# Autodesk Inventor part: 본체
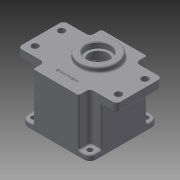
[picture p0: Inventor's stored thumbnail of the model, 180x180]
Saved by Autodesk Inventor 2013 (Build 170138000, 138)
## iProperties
Created: 2015-07
Part Number: 본체
Material: 일반
Document SubType Name: Modeling
Designer: user
Density: 1 g/cm^3
Author: user
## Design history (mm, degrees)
sketch "스케치3"
  geometry: L1 (45, 30)-(45, -30); L2 (30, -45)-(-30, -45); L3 (-45, -30)-(-45, 30); L4 (30, 45)-(30, 30); L5 (30, 30)-(45, 30); L6 (-30, 30)-(-45, 30); L7 (-30, 45)-(-30, 30); L8 (-30, -30)-(-45, -30); L9 (-30, -45)-(-30, -30); L10 (30, -45)-(30, -30); L11 (30, -30)-(45, -30); L12 (30, 45)-(-30, 45); 3 further points
  constraints: 24 end point, 2 midpoint, 2 parallel, 1 horizontal alignment, 1 perpendicular, 1 vertical alignment
  dimensions: "d7" = 15 distance of L4.start L4.end; "d8" = 15 distance of L4.end L1.start; "d9" = 15 distance of L6.start L3.end; "d10" = 60 distance of L4.start L7.start; "d11" = 90 distance between parallel lines of L1 L3; "d12" = 45 distance from line of L1 point (0, 0); "d13" = 15 distance between parallel lines of L3 L9; "d14" = 15 distance between parallel lines of L1 L10; "d15" = 60 distance of L2.start L2.end; "d16" = 15 distance between parallel lines of L2 L8; "d17" = 15 distance between parallel lines of L2 L11; "d18" = 15 distance between parallel lines of L12 L6; "d19" = 90 distance between parallel lines of L2 L12; "d20" = 45 distance from line of L12 point (0, 0); "d21" = 30 distance from line of point (0, 0) L4; "d22" = 45 distance from line of point (0, -45) L1
extrude "돌출2" new body sketch "스케치3" distance "d23" = 70; taper "d24" = 0 deg
sketch "스케치4"
  geometry: L1 (-30, 45)-(-30, 30) reference; L2 (-30, 30)-(-45, 30) reference; L3 (-45, 30)-(-45, -30) reference; L4 (-45, -30)-(-30, -30) reference; L5 (-30, -30)-(-30, -45) reference; L6 (-30, -45)-(30, -45) reference; L7 (30, -45)-(30, -30) reference; L8 (30, -30)-(45, -30) reference; L9 (45, -30)-(45, 30) reference; L10 (45, 30)-(30, 30) reference; L11 (30, 30)-(30, 45) reference; L12 (30, 45)-(-30, 45) reference; L13 (0, 0)-(0, 45); L14 (0, 45)-(30, 45); L15 (30, 45)-(30, 30); L16 (30, 30)-(65, 30); L17 (65, 30)-(65, -30); L18 (65, -30)-(30, -30); L19 (30, -30)-(30, -45); L20 (30, -45)-(0, -45); L21 (0, 45)-(-30, 45); L22 (-30, 45)-(-30, 30); L23 (-30, 30)-(-65, 30); L24 (-65, 30)-(-65, -30); L25 (-65, -30)-(-30, -30); L26 (-30, -30)-(-30, -45); L27 (-30, -45)-(0, -45)
  constraints: 30 end point, 3 perpendicular, 2 collinear, 2 midpoint, 2 symmetric about line
  dimensions: "d25" = 30 distance of L13.end L11.end (derived); "d26" = 35 distance of L10.end L16.end; "d27" = 60 distance of L16.end L17.end; "d28" = 35 distance of L17.end L7.end (derived); "d29" = 15 distance of L7.end L6.end (derived)
extrude "돌출3" join sketch "스케치4" distance "d30" = 12; taper "d31" = 0 deg
sketch "스케치5"
  geometry: L1 (-45, 45)-(45, 45); L2 (45, 45)-(45, -45); L3 (45, -45)-(-45, -45); L4 (-45, -45)-(-45, 45); 3 further points
  constraints: 8 end point, 2 midpoint, 2 parallel, 1 horizontal, 1 horizontal alignment, 1 perpendicular, 1 vertical alignment
  dimensions: "d32" = 90 distance of L2.end L3.end; "d33" = 90 distance of L1.end L2.end
extrude "돌출4" join sketch "스케치5" distance "d34" = 7; taper "d35" = 0 deg
fillet "모깎기1" dims "d36" = 5
fillet "모깎기2" dims "d37" = 8
sketch "스케치6"
  geometry: C1 r 40 at (0, 0); 1 further point
  constraints: 1 centre point, 1 coincident
  dimensions: "d38" = 80 diameter of C1
extrude "돌출5" cut sketch "스케치6" distance "d39" = 9; taper "d40" = 0 deg
sketch "스케치7"
  geometry: L1 (0, 0)-(24.749, 24.749); L2 (0, 0)-(35, 0); C1 r 40 at (0, 0) reference; A1 r 4 centre (24.749, 24.749) between (21.809, 27.462) and (27.462, 21.809); A2 r 3.5 centre (19.238, 29.836) between (21.762, 27.412) and (21.134, 32.777); A3 r 3.5 centre (29.836, 19.238) between (32.777, 21.134) and (27.412, 21.762); A4 r 3.5 centre (-29.836, 19.238) between (-27.412, 21.762) and (-32.777, 21.134); A5 r 4 centre (-24.749, 24.749) between (-27.462, 21.809) and (-21.809, 27.462); A6 r 3.5 centre (-19.238, 29.836) between (-21.134, 32.777) and (-21.762, 27.412); A7 r 3.5 centre (-19.238, -29.836) between (-21.762, -27.412) and (-21.134, -32.777); A8 r 4 centre (-24.749, -24.749) between (-21.809, -27.462) and (-27.462, -21.809); A9 r 3.5 centre (-29.836, -19.238) between (-32.777, -21.134) and (-27.412, -21.762); A10 r 3.5 centre (29.836, -19.238) between (27.412, -21.762) and (32.777, -21.134); A11 r 4 centre (24.749, -24.749) between (27.462, -21.809) and (21.809, -27.462); A12 r 3.5 centre (19.238, -29.836) between (21.134, -32.777) and (21.762, -27.412); A13 r 39 centre (0, 0) between (21.134, 32.777) and (-21.134, 32.777); A14 r 39 centre (0, 0) between (-32.777, 21.134) and (-32.777, -21.134); A15 r 39 centre (0, 0) between (-21.134, -32.777) and (21.134, -32.777); A16 r 39 centre (0, 0) between (32.777, -21.134) and (32.777, 21.134)
  constraints: 40 point on circle, 16 centre point, 5 tangent, 4 end point, 3 coincident, 1 equal length, 1 horizontal, 49 other
  dimensions: "d43" = 35 distance of L1.start L1.end; "d44" = 45 deg angle of L2 L1; "d45" = 8 diameter of A1; "d46" = 7 diameter of A2; "d47" = 7 diameter of A3; "d50" = 360 deg dimension on A13.centre A2.centre (derived); "d52" = 21.76231 distance from line of A3.end L2; "d53" = 21.76231 distance from line of A10.start L2
extrude "돌출6" cut sketch "스케치7" distance "d54" = 52; taper "d55" = 0 deg
hole "구멍1" diameter "d58" = 3.459; stored, may be unused: countersink angle "d62" = 90 deg, drill point angle "d64" = 118 deg; dims "d56" = 10, "d57" = 10, "d59" = 12, "d60" = 4, "d61" = 2, "d63" = 15
sketch "스케치9"
  geometry: L1 (0, 0)-(0, 11); L2 (0, 0)-(0, -20); A1 r 39 centre (0, 0) between (32.777, -21.134) and (32.777, 21.134) reference; A2 r 20.5 centre (0, 11) between (11.115, -6.225) and (-11.115, -6.225); A3 r 14 centre (0, -20) between (-10.493, -10.732) and (10.493, -10.732); A4 r 3 centre (12.742, -8.746) between (11.115, -6.225) and (10.493, -10.732); A5 r 3 centre (-12.742, -8.746) between (-10.493, -10.732) and (-11.115, -6.225)
  constraints: 8 point on circle, 4 centre point, 4 end point, 4 tangent, 2 coincident, 1 collinear, 1 vertical
  dimensions: "d68" = 11 distance of L1.start L1.end; "d69" = 41 diameter of A2; "d70" = 20 distance of L1.start L2.end; "d71" = 28 diameter of A3; "d72" = 6 diameter of A4; "d73" = 6 diameter of A5
extrude "돌출7" join sketch "스케치9" distance "d74" = 7; taper "d75" = 0 deg
sketch "스케치10"
  geometry: L1 (-30, 30)-(-60, 30) reference; L2 (0, 0)-(0, 11); C1 r 25 at (0, 11)
  constraints: 2 end point, 1 centre point, 1 coincident, 1 perpendicular
  dimensions: "d76" = 11 distance of L2.start L2.end; "d77" = 50 diameter of C1
extrude "돌출8" join sketch "스케치10" distance "d78" = 7; taper "d79" = 0 deg
hole "구멍2" diameter "d82" = 25; stored, may be unused: countersink angle "d86" = 90 deg, drill point angle "d88" = 118 deg; dims "d80" = 10, "d81" = 10, "d83" = 12, "d84" = 32, "d85" = 8, "d87" = 15
sketch "스케치11"
  geometry: C1 r 12.5 at (0, 11) reference; C2 r 17.5 at (0, 11); A1 r 20.5 centre (0, 11) between (11.115, -6.225) and (-11.115, -6.225) reference; 1 further point
  constraints: 1 centre point, 1 coincident
  dimensions: "d89" = 35 diameter of C2
extrude "돌출9" cut sketch "스케치11" distance "d90" = 10; taper "d91" = 0 deg
hole "구멍3" diameter "d94" = 19; stored, may be unused: countersink angle "d98" = 90 deg, drill point angle "d100" = 0 deg; dims "d92" = 10, "d93" = 10, "d95" = 12, "d96" = 22, "d97" = 7, "d99" = 8
fillet "모깎기3" dims "d101" = 2
fillet "모깎기4" dims "d102" = 2
fillet "모깎기5" dims "d103" = 2
chamfer "모따기1" distance "d104" = 1; stored, may be unused: second distance "d105" = 2, angle "d106" = 45 deg
fillet "모깎기6" dims "d107" = 1
chamfer "모따기2" distance "d108" = 1; stored, may be unused: second distance "d109" = 2, angle "d110" = 45 deg
fillet "모깎기7" dims "d111" = 0.3
fillet "모깎기8" dims "d112" = 5
fillet "모깎기9" dims "d113" = 2
fillet "모깎기10" dims "d114" = 2
sketch "스케치13"
  geometry: L1 (35, 30)-(43.536, 30) reference; L2 (60, 28)-(47, 28) reference; L3 (63, -25)-(63, 25) reference; L4 (47, -28)-(60, -28) reference; L5 (43.536, -30)-(35, -30) reference; L6 (30, -35)-(30, -43) reference; L7 (28, -45)-(-28, -45) reference; L8 (-30, -43)-(-30, -35) reference; L9 (-35, -30)-(-43, -30) reference; L10 (-47, -28)-(-47, 28) reference; L11 (-43, 30)-(-35, 30) reference; L12 (-30, 35)-(-30, 43) reference; L13 (-28, 45)-(28, 45) reference; L14 (30, 43)-(30, 35) reference; L15 (47, 28)-(47, -28) reference; L16 (-60, -28)-(-47, -28) reference; L17 (-63, 25)-(-63, -25) reference; L18 (-47, 28)-(-60, 28) reference; L19 (65, -25)-(65, 25) reference; L20 (65, 0)-(65, 17.5); L21 (65, 17.5)-(55, 17.5); C1 r 11 at (0, -20) reference; C2 r 17.5 at (0, 11) reference; C3 r 4.5 at (55, 17.5); A1 r 5 centre (35, 35) between (30, 35) and (35, 30) reference; A2 r 3 centre (60, 25) between (63, 25) and (60, 28) reference; A3 r 3 centre (60, -25) between (60, -28) and (63, -25) reference; A4 r 5 centre (35, -35) between (35, -30) and (30, -35) reference; A5 r 2 centre (28, -43) between (28, -45) and (30, -43) reference; A6 r 2 centre (-28, -43) between (-30, -43) and (-28, -45) reference; A7 r 5 centre (-35, -35) between (-30, -35) and (-35, -30) reference; A8 r 2 centre (-43, -28) between (-44, -29.732) and (-43, -30) reference; A9 r 2 centre (-43, 28) between (-43, 30) and (-44, 29.732) reference; A10 r 5 centre (-35, 35) between (-35, 30) and (-30, 35) reference; A11 r 2 centre (-28, 43) between (-28, 45) and (-30, 43) reference; A12 r 2 centre (28, 43) between (30, 43) and (28, 45) reference; A13 r 3 centre (-60, -25) between (-63, -25) and (-60, -28) reference; A14 r 3 centre (-60, 25) between (-60, 28) and (-63, 25) reference; A15 r 14 centre (0, -20) between (-10.493, -10.732) and (10.493, -10.732) reference; A16 r 3 centre (-12.742, -8.746) between (-10.493, -10.732) and (-11.115, -6.225) reference; A17 r 20.5 centre (0, 11) between (11.115, -6.225) and (-11.115, -6.225) reference; A18 r 3 centre (12.742, -8.746) between (11.115, -6.225) and (10.493, -10.732) reference; A19 r 3.5 centre (-29.836, -19.238) between (-32.777, -21.134) and (-27.462, -21.809) reference; A20 r 4 centre (-24.749, -24.749) between (-21.809, -27.462) and (-27.462, -21.809) reference; A21 r 3.5 centre (-19.238, -29.836) between (-21.809, -27.462) and (-21.134, -32.777) reference; A22 r 39 centre (0, 0) between (-21.134, -32.777) and (21.134, -32.777) reference; A23 r 3.5 centre (19.238, -29.836) between (21.134, -32.777) and (21.809, -27.462) reference; A24 r 4 centre (24.749, -24.749) between (27.462, -21.809) and (21.809, -27.462) reference; A25 r 3.5 centre (29.836, -19.238) between (27.462, -21.809) and (32.777, -21.134) reference; A26 r 39 centre (0, 0) between (32.777, -21.134) and (32.777, 21.134) reference; A27 r 3.5 centre (29.836, 19.238) between (32.777, 21.134) and (27.462, 21.809) reference; A28 r 4 centre (24.749, 24.749) between (21.809, 27.462) and (27.462, 21.809) reference; A29 r 3.5 centre (19.238, 29.836) between (21.809, 27.462) and (21.134, 32.777) reference; A30 r 39 centre (0, 0) between (21.134, 32.777) and (-21.134, 32.777) reference; A31 r 3.5 centre (-19.238, 29.836) between (-21.134, 32.777) and (-21.809, 27.462) reference; A32 r 4 centre (-24.749, 24.749) between (-27.462, 21.809) and (-21.809, 27.462) reference; A33 r 3.5 centre (-29.836, 19.238) between (-27.462, 21.809) and (-32.777, 21.134) reference; A34 r 39 centre (0, 0) between (-32.777, 21.134) and (-32.777, -21.134) reference; 1 further point
  constraints: 4 end point, 1 centre point, 1 coincident, 1 midpoint, 1 perpendicular, 1 point on line, 4 other
  dimensions: "d118" = 17.5 distance of L20.start L20.end; "d119" = 10 distance of L20.end L21.end; "d120" = 9 diameter of C3
extrude "돌출10" cut sketch "스케치13" stored distance "d121" = 10; taper "d122" = 0 deg
sketch "스케치14"
  geometry: L1 (45, 28.536)-(45, -28.536) reference; L2 (43, -37)-(43, -32) reference; L3 (32, -43)-(37, -43) reference; L4 (28.536, -45)-(-28.536, -45) reference; L5 (-37, -43)-(-32, -43) reference; L6 (-43, -32)-(-43, -37) reference; L7 (-45, -28.536)-(-45, 28.536) reference; L8 (-43, 37)-(-43, 32) reference; L9 (-32, 43)-(-37, 43) reference; L10 (-28.536, 45)-(28.536, 45) reference; L11 (37, 43)-(32, 43) reference; L12 (43, 32)-(43, 37) reference; L13 (43, -32)-(35, -32) reference; L14 (32, -35)-(32, -43) reference; L15 (-32, -43)-(-32, -35) reference; L16 (-35, -32)-(-43, -32) reference; L17 (-43, 32)-(-35, 32) reference; L18 (-32, 35)-(-32, 43) reference; L19 (32, 43)-(32, 35) reference; L20 (35, 32)-(43, 32) reference; C1 r 40 at (0, 0) reference; C2 r 3.5 at (37, 37); A1 r 6 centre (37, -37) between (37, -43) and (43, -37) reference; A2 r 6 centre (-37, -37) between (-43, -37) and (-37, -43) reference; A3 r 6 centre (-37, 37) between (-37, 43) and (-43, 37) reference; A4 r 6 centre (37, 37) between (43, 37) and (37, 43) reference; A5 r 3 centre (35, -35) between (35, -32) and (32, -35) reference; A6 r 3 centre (-35, -35) between (-32, -35) and (-35, -32) reference; A7 r 3 centre (-35, 35) between (-35, 32) and (-32, 35) reference; A8 r 3 centre (35, 35) between (32, 35) and (35, 32) reference; 1 further point
  constraints: 1 centre point, 1 coincident, 8 other
  dimensions: "d125" = 7 diameter of C2
extrude "돌출11" cut sketch "스케치14" stored distance "d126" = 10; taper "d127" = 0 deg
sketch "스케치15"
  geometry: L1 (-28, -45)-(28, -45) reference; L2 (-30, -35)-(-30, -43) reference; L3 (0, 0)-(0, -40.303); 1 further point
  constraints: 2 end point, 1 parallel, 1 point on line, 1 other
  dimensions: "d128" = 15 distance from line of point (0, -30) L1
feature "엠보싱1" sketch "스케치15" dims "d129" = 0.5, "d130" = 0
node "솔리드2"
pattern_circular "원형 패턴1" dims angle "d66" = 360 deg
mirror "대칭1"
mirror "대칭2"
mirror "대칭3"
mirror "대칭4"
node "절단 모서리 투영1"
node "절단 모서리 투영2"
other parameters: "d41" = 78
